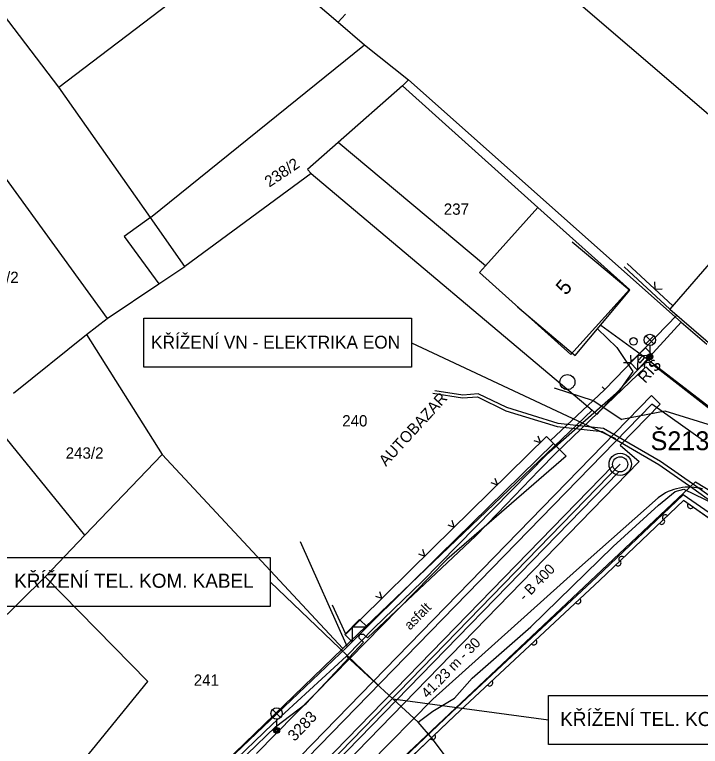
# Model space of a CAD drawing. Extents: x -601580 to 4, y -1204314 to 4.
# Drawn here: x -600487.22 to -600441.72, y -1203792.72 to -1203744.15 of the extents above; entities that cross this region are included whole.
import ezdxf

# ---------------------------------------------------------------- set-up
doc = ezdxf.new("R2010")
doc.units = 0
for name, color, linetype in [('00-EON NN', 7, 'Continuous'), ('00-EON VN', 7, 'Continuous'), ('00-KN-HRANICE PARCEL', 7, 'Continuous'), ('00-KN-PARC. CISLA', 7, 'Continuous'), ('00-KN-VNITRNI KRESBA', 7, 'Continuous'), ('00-POLOHOPIS', 7, 'Continuous'), ('00-SITE KOM. KABEL', 7, 'Continuous'), ('00-VAK-KANAL-POTRUBI', 7, 'Continuous'), ('00-VAK-VODA-RAD IGIS', 7, 'Continuous'), ('11-REKONSTRUKCE  VYKOP', 7, 'Continuous'), ('11-REKONSTRUKCE KANALIZACE', 7, 'Continuous'), ('11-REKONSTRUKCE KANALIZACE OSA', 7, 'Continuous'), ('11-REKONSTRUKCE KANALIZACE POPIS', 7, 'Continuous'), ('11-REKONSTRUKCE VODOVOD', 7, 'Continuous'), ('11-REKONSTRUKCE VODOVOD POPIS', 7, 'Continuous'), ('Vrstva 26', 7, 'Continuous'), ('Vrstva 27', 7, 'Continuous'), ('Vrstva 28', 7, 'Continuous'), ('Vrstva 33', 7, 'Continuous'), ('Vrstva 8', 7, 'Continuous'), ('Vrstva 9', 7, 'Continuous')]:
    doc.layers.add(name, color=color, linetype=linetype)

# ---------------------------------------------------------------- blocks, each defined once
blk = doc.blocks.new('6.14A_1004')
at = {"layer": 'Vrstva 28'}
blk.add_circle((0, 0), 0.25, dxfattribs=at)
blk = doc.blocks.new('6.20D_492')
at = {"layer": 'Vrstva 27'}
blk.add_circle((0, 0), 0.5, dxfattribs=at)
blk = doc.blocks.new('6.560_1100')
at = {"layer": 'Vrstva 33'}
for p, q in [((-0.265, 0.86), (0.265, 1.39)), ((-0.265, 1.39), (0.265, 0.86)), ((0, 0.75), (0, 0))]:
    blk.add_line(p, q, dxfattribs=at)
for centre, radius in [((0, 1.125), 0.375), ((0, 0), 0.2), ((0, 0), 0.145), ((0, 0), 0.0876)]:
    blk.add_circle(centre, radius, dxfattribs=at)
blk = doc.blocks.new('VSTUP_174')
at = {"layer": 'Vrstva 8'}
blk.add_line((0, 0.25), (0, 0), dxfattribs=at)
blk = doc.blocks.new('6.560_1102')
at = {"layer": 'Vrstva 33'}
for p, q in [((-0.265, 0.86), (0.265, 1.39)), ((-0.265, 1.39), (0.265, 0.86)), ((0, 0.75), (0, 0))]:
    blk.add_line(p, q, dxfattribs=at)
for centre, radius in [((0, 1.125), 0.375), ((0, 0), 0.2), ((0, 0), 0.145), ((0, 0), 0.0876)]:
    blk.add_circle(centre, radius, dxfattribs=at)
blk = doc.blocks.new('NN630')
at = {"layer": 'Vrstva 9'}
for points in [[(-3, -700), (-703, 0)], [(-703, -700), (-703, 0), (697, 0), (697, -700)], [(-3, -700), (697, 0)], [(-703, -700), (697, -700)]]:
    blk.add_lwpolyline(points, dxfattribs=at)

msp = doc.modelspace()

# ---------------------------------------------------------------- linework, layer by layer
at = {"layer": '00-EON NN'}
msp.add_lwpolyline([(-600473.672, -1203795.059), (-600469.91, -1203791.43), (-600467.871, -1203789.879), (-600464.07, -1203785.817), (-600464.347, -1203785.548), (-600464.327, -1203785.286), (-600464.065, -1203785.278), (-600463.799, -1203785.523), (-600456.609, -1203778.75), (-600455.185, -1203777.274), (-600452.407, -1203774.395), (-600451.32, -1203773.27), (-600447.396, -1203769.512), (-600445.375, -1203767.577), (-600445.434, -1203767.516), (-600445.39, -1203767.27), (-600445.152, -1203767.233), (-600444.955, -1203767.436), (-600444.789, -1203767.441), (-600443.789, -1203768.219), (-600439.988, -1203771.191)], dxfattribs=at)
at = {"layer": '00-EON VN'}
for points in [[(-600459.477, -1203769.291), (-600457.511, -1203769.594), (-600456.508, -1203769.518), (-600454.624, -1203770.445), (-600451.211, -1203771.488), (-600448.233, -1203771.815), (-600444.486, -1203774.019), (-600442.217, -1203775.59), (-600438.167, -1203778.496), (-600424.472, -1203787.735), (-600416.801, -1203792.528), (-600411.123, -1203796.487), (-600404.975, -1203801.537), (-600404.82, -1203801.644), (-600404.96, -1203802.62)], [(-600383.25, -1203783.59), (-600384.36, -1203785.06), (-600387.363, -1203790.788), (-600387.636, -1203791.819), (-600388.781, -1203794.246), (-600391.141, -1203798.544), (-600394.408, -1203804.965), (-600395.164, -1203806.243), (-600395.912, -1203806.852), (-600396.541, -1203806.795), (-600400.796, -1203804.12), (-600404.813, -1203801.302), (-600410.985, -1203796.316), (-600416.678, -1203792.351), (-600424.36, -1203787.555), (-600438.08, -1203778.28), (-600442.027, -1203775.462), (-600444.357, -1203773.807), (-600448.151, -1203771.631), (-600451.152, -1203771.298), (-600454.57, -1203770.237), (-600456.457, -1203769.325), (-600457.482, -1203769.405), (-600459.327, -1203769.119)]]:
    msp.add_lwpolyline(points, dxfattribs=at)
at = {"layer": '00-KN-HRANICE PARCEL'}
for p, q in [((-600478.21, -1203757.62), (-600464, -1203746.15)), ((-600464, -1203746.15), (-600461.08, -1203748.49)), ((-600461.08, -1203748.49), (-600442.99, -1203764.57)), ((-600467.55, -1203754.71), (-600475.93, -1203760.88)), ((-600467.55, -1203754.71), (-600448.91, -1203770.42)), ((-600482.45, -1203765.39), (-600481.08, -1203764.32)), ((-600442.99, -1203764.57), (-600441.29, -1203766.03)), ((-600487.29, -1203769.27), (-600482.45, -1203765.39)), ((-600482.45, -1203765.39), (-600477.42, -1203773.36)), ((-600465.44, -1203786.23), (-600448.91, -1203770.42)), ((-600482.55, -1203778.7), (-600489.05, -1203770.73)), ((-600477.42, -1203773.36), (-600482.55, -1203778.7)), ((-600477.42, -1203773.36), (-600465.44, -1203786.23))]:
    msp.add_line(p, q, dxfattribs=at)
for points in [[(-600469.34, -1203723.1), (-600466.22, -1203727.76), (-600462.39, -1203731.53), (-600461.96, -1203731.92), (-600457.59, -1203735.9), (-600452.74, -1203740.82), (-600433.78, -1203757.11)], [(-600480.16, -1203730.41), (-600471.78, -1203739.46), (-600469.52, -1203741.43), (-600465.75, -1203744.65), (-600464, -1203746.15)], [(-600478.21, -1203757.62), (-600484.29, -1203748.96), (-600487.61, -1203744.61), (-600491.59, -1203739.41)], [(-600461.08, -1203748.49), (-600461.48, -1203748.88), (-600465.75, -1203752.64), (-600467.78, -1203754.43), (-600467.55, -1203754.71)], [(-600495.99, -1203757.53), (-600497.89, -1203754.85), (-600498.89, -1203753.29), (-600498.57, -1203753.07), (-600497.03, -1203755.41), (-600490.66, -1203751.13), (-600481.08, -1203764.32)], [(-600475.93, -1203760.88), (-600478.05, -1203757.85), (-600478.21, -1203757.62)], [(-600481.08, -1203764.32), (-600477.64, -1203762.03), (-600475.93, -1203760.88)], [(-600448.91, -1203770.42), (-600448.58, -1203770.7), (-600442.99, -1203764.57)], [(-600490.56, -1203829.3), (-600473.65, -1203806.86), (-600467.29, -1203799), (-600442.04, -1203775.17), (-600437.14, -1203778.16)], [(-600482.55, -1203778.7), (-600485.2, -1203781.47), (-600490.18, -1203786.39), (-600492.01, -1203788.21), (-600491.04, -1203789.24), (-600495.44, -1203792.84)], [(-600486.72, -1203810.21), (-600473.25, -1203793.78), (-600465.44, -1203786.23)]]:
    msp.add_lwpolyline(points, dxfattribs=at)
at = {"layer": '00-KN-VNITRNI KRESBA'}
for p, q in [((-600484.29, -1203748.96), (-600471.78, -1203739.46)), ((-600465.27, -1203744.13), (-600465.75, -1203744.65)), ((-600461.48, -1203748.88), (-600452.5, -1203756.96)), ((-600455.97, -1203760.82), (-600465.75, -1203752.64)), ((-600455.97, -1203760.82), (-600452.5, -1203756.96)), ((-600452.5, -1203756.96), (-600446.43, -1203762.41)), ((-600478.21, -1203757.62), (-600479.94, -1203758.89)), ((-600479.94, -1203758.89), (-600477.64, -1203762.03)), ((-600456.37, -1203761.27), (-600455.97, -1203760.82)), ((-600450.31, -1203766.72), (-600456.37, -1203761.27)), ((-600446.43, -1203762.41), (-600450.31, -1203766.72)), ((-600478.38, -1203788.41), (-600485.2, -1203781.47)), ((-600489.46, -1203802.03), (-600478.38, -1203788.41))]:
    msp.add_line(p, q, dxfattribs=at)
at = {"layer": '00-POLOHOPIS'}
for p, q in [((-600450.221, -1203759.23), (-600446.395, -1203762.449)), ((-600440.476, -1203759.931), (-600443.745, -1203763.714)), ((-600446.581, -1203760.675), (-600443.548, -1203763.486)), ((-600443.745, -1203763.714), (-600446.785, -1203760.896)), ((-600450.034, -1203766.775), (-600446.395, -1203762.449)), ((-600453.86, -1203763.556), (-600450.034, -1203766.775)), ((-600448.055, -1203769.043), (-600443.291, -1203764.106)), ((-600443.745, -1203763.714), (-600432.317, -1203773.59)), ((-600445.86, -1203767.128), (-600445.567, -1203766.796)), ((-600445.711, -1203767.261), (-600445.418, -1203766.929)), ((-600445.418, -1203766.929), (-600445.567, -1203766.796)), ((-600445.86, -1203767.128), (-600445.721, -1203767.261)), ((-600451.431, -1203768.926), (-600448.827, -1203769.768)), ((-600448.827, -1203769.768), (-600448.055, -1203769.043)), ((-600448.827, -1203769.768), (-600448.055, -1203769.043)), ((-600451.671, -1203772.418), (-600448.827, -1203769.768)), ((-600451.671, -1203772.418), (-600448.827, -1203769.768)), ((-600448.827, -1203769.768), (-600446.92, -1203771.019)), ((-600444.049, -1203770.469), (-600446.92, -1203771.019)), ((-600439.816, -1203771.808), (-600444.049, -1203770.469)), ((-600459.471, -1203779.568), (-600451.925, -1203772.158)), ((-600451.925, -1203772.158), (-600451.47, -1203772.622)), ((-600459.02, -1203780.036), (-600451.47, -1203772.622)), ((-600451.47, -1203772.622), (-600450.627, -1203773.461)), ((-600450.627, -1203773.461), (-600458.536, -1203780.325)), ((-600444.521, -1203776.225), (-600449.943, -1203781.031)), ((-600442.871, -1203776.021), (-600448.591, -1203781.475)), ((-600430.741, -1203784.52), (-600442.871, -1203776.021)), ((-600442.841, -1203776.408), (-600448.383, -1203781.692)), ((-600430.913, -1203784.765), (-600442.841, -1203776.408)), ((-600468.263, -1203779.127), (-600465.151, -1203786.129)), ((-600464.272, -1203784.301), (-600459.471, -1203779.568)), ((-600463.811, -1203784.759), (-600459.02, -1203780.036)), ((-600458.536, -1203780.325), (-600466.057, -1203787.997)), ((-600449.943, -1203781.031), (-600459.469, -1203789.593)), ((-600448.591, -1203781.475), (-600458.24, -1203790.484)), ((-600448.386, -1203781.694), (-600458.041, -1203790.709)), ((-600465.237, -1203785.287), (-600466.118, -1203783.347)), ((-600465.237, -1203785.287), (-600464.272, -1203784.301)), ((-600465.151, -1203786.129), (-600463.811, -1203784.759)), ((-600473.056, -1203793.647), (-600465.151, -1203786.129)), ((-600466.057, -1203787.997), (-600471.165, -1203793.196)), ((-600459.469, -1203789.593), (-600467.784, -1203798.007)), ((-600458.24, -1203790.484), (-600464.245, -1203796.188)), ((-600458.041, -1203790.709), (-600464.03, -1203796.398))]:
    msp.add_line(p, q, dxfattribs=at)
for points in [[(-600446.581, -1203760.675), (-600443.548, -1203763.486)], [(-600444.766, -1203761.88), (-600444.747, -1203762.374), (-600444.253, -1203762.356)], [(-600448.055, -1203769.043), (-600443.291, -1203764.106)], [(-600446.814, -1203767.253), (-600446.319, -1203767.244), (-600446.328, -1203766.749)], [(-600459.471, -1203779.568), (-600451.925, -1203772.158)], [(-600452.759, -1203772.416), (-600452.336, -1203772.562), (-600452.473, -1203772.136)], [(-600451.925, -1203772.158), (-600451.47, -1203772.622)], [(-600455.613, -1203775.219), (-600455.19, -1203775.364), (-600455.328, -1203774.939)], [(-600448.383, -1203781.692), (-600442.841, -1203776.408)], [(-600448.383, -1203781.692), (-600442.841, -1203776.408)], [(-600448.383, -1203781.692), (-600442.841, -1203776.408)], [(-600430.913, -1203784.765), (-600442.841, -1203776.408)], [(-600458.467, -1203778.021), (-600458.044, -1203778.167), (-600458.182, -1203777.741)], [(-600464.272, -1203784.301), (-600459.471, -1203779.568)], [(-600460.422, -1203779.944), (-600459.999, -1203780.089), (-600460.138, -1203779.663)], [(-600458.041, -1203790.709), (-600448.386, -1203781.694)], [(-600458.041, -1203790.709), (-600448.386, -1203781.694)], [(-600463.271, -1203782.752), (-600462.848, -1203782.897), (-600462.986, -1203782.472)], [(-600458.041, -1203790.709), (-600464.03, -1203796.398)]]:
    msp.add_lwpolyline(points, dxfattribs=at)
for centre, radius, start, end in [((-600442.471, -1203778.842), 3.324, 74.039, 128.0674), ((-600442.379, -1203776.732), 0.2, 144.9827, 324.9856), ((-600444.288, -1203777.788), 0.2, 223.6334, 43.6362), ((-600444.04, -1203777.552), 0.2, 43.6334, 223.6362), ((-600446.935, -1203780.312), 0.2, 43.6334, 223.6362), ((-600447.183, -1203780.548), 0.2, 223.6334, 43.6362), ((-600449.848, -1203783.059), 0.2, 223.0352, 43.0381), ((-600452.771, -1203785.789), 0.2, 223.0352, 43.0381), ((-600455.695, -1203788.519), 0.2, 223.0352, 43.0381), ((-600459.491, -1203792.086), 0.2, 223.527, 43.5299)]:
    msp.add_arc(centre, radius, start, end, dxfattribs=at)
at = {"layer": '00-SITE KOM. KABEL'}
for points in [[(-600448.32, -1203764.77), (-600445.41, -1203766.9), (-600434.97, -1203774.92), (-600422.32, -1203783.12), (-600413.93, -1203789.04), (-600405.18, -1203794.93), (-600400.25, -1203797.98), (-600398.96, -1203798.36), (-600397.12, -1203797.36), (-600388.96, -1203781.95), (-600378.33, -1203762.13), (-600375.93, -1203758.23), (-600373.1, -1203754.01), (-600370.24, -1203749.96), (-600363.35, -1203740.04), (-600357.38, -1203731.69), (-600349.33, -1203720.15), (-600345.8, -1203715.19), (-600340.07, -1203706.96), (-600329.02, -1203689.27)], [(-600448.55, -1203765.01), (-600447.27, -1203766.25), (-600446.21, -1203767.84)], [(-600446.21, -1203767.84), (-600447.14, -1203769.15), (-600451.9, -1203773.36), (-600460.17, -1203781.78), (-600463.36, -1203784.86)], [(-600447.14, -1203769.15), (-600451.9, -1203773.36)], [(-600460.44, -1203791.11), (-600459.46, -1203790.39), (-600458.03, -1203789.53), (-600456.87, -1203788.19), (-600452.97, -1203784.79), (-600447.51, -1203779.45), (-600444.5, -1203776.72), (-600443.4, -1203775.81), (-600442.82, -1203775.66), (-600440.03, -1203777)], [(-600463.36, -1203784.86), (-600465.19, -1203786.74)], [(-600477.51, -1203798.97), (-600477.33, -1203799.12), (-600473.04, -1203794.08), (-600470.1, -1203791.26), (-600465.19, -1203786.74)], [(-600460.44, -1203791.11), (-600465.19, -1203786.74)], [(-600460.44, -1203791.11), (-600465.19, -1203786.74)], [(-600459.49, -1203792.23), (-600460.44, -1203791.11)], [(-600456.27, -1203796.31), (-600456.73, -1203795.91), (-600459.49, -1203792.23)], [(-600455.71, -1203797.64), (-600456.27, -1203796.31), (-600456.73, -1203795.91), (-600459.49, -1203792.23)]]:
    msp.add_lwpolyline(points, dxfattribs=at)
at = {"layer": '00-VAK-KANAL-POTRUBI'}
msp.add_circle((-600447.04, -1203774.002), 0.5, dxfattribs=at)
at = {"layer": '00-VAK-VODA-RAD IGIS'}
msp.add_lwpolyline([(-600395.742, -1203804.116), (-600404.972, -1203798.52), (-600440.983, -1203772.83), (-600444.948, -1203770.012)], dxfattribs=at)
at = {"layer": '11-REKONSTRUKCE  VYKOP'}
for p, q in [((-600444.956, -1203769.446), (-600444.383, -1203770.004)), ((-600447.033, -1203772.727), (-600445.772, -1203773.818)), ((-600445.772, -1203773.818), (-600475.196, -1203804.047))]:
    msp.add_line(p, q, dxfattribs=at)
for points in [[(-600500.747, -1203836.125), (-600477.095, -1203802.472), (-600444.956, -1203769.446)], [(-600447.033, -1203772.727), (-600444.383, -1203770.004)]]:
    msp.add_lwpolyline(points, dxfattribs=at)
at = {"layer": '11-REKONSTRUKCE KANALIZACE'}
for p, q in [((-600447.53, -1203774.104), (-600475.521, -1203802.862)), ((-600447.129, -1203774.495), (-600475.12, -1203803.252))]:
    msp.add_line(p, q, dxfattribs=at)
for radius in [0.74, 0.5]:
    msp.add_circle((-600447.04, -1203774.002), radius, dxfattribs=at)
at = {"layer": '11-REKONSTRUKCE KANALIZACE OSA'}
msp.add_line((-600447.04, -1203774.002), (-600475.798, -1203803.548), dxfattribs=at)
at = {"layer": '11-REKONSTRUKCE KANALIZACE POPIS'}
msp.add_line((-600451.8, -1203790.984), (-600462.129, -1203789.593), dxfattribs=at)
msp.add_lwpolyline([(-600451.8, -1203789.358), (-600434.043, -1203789.358), (-600434.043, -1203792.609), (-600451.8, -1203792.609)], close=True, dxfattribs=at)
at = {"layer": '11-REKONSTRUKCE VODOVOD'}
msp.add_lwpolyline([(-600500.42, -1203836.355), (-600476.786, -1203802.728), (-600444.948, -1203770.012)], dxfattribs=at)
at = {"layer": '11-REKONSTRUKCE VODOVOD POPIS'}
for p, q in [((-600460.886, -1203765.935), (-600447.342, -1203772.283)), ((-600470.271, -1203781.806), (-600463.098, -1203788.665))]:
    msp.add_line(p, q, dxfattribs=at)
for points in [[(-600478.644, -1203764.309), (-600460.886, -1203764.309), (-600460.886, -1203767.561), (-600478.644, -1203767.561)], [(-600488.028, -1203780.18), (-600470.271, -1203780.18), (-600470.271, -1203783.431), (-600488.028, -1203783.431)]]:
    msp.add_lwpolyline(points, close=True, dxfattribs=at)

# ---------------------------------------------------------------- block references
at = {"layer": '00-POLOHOPIS'}
for name, p in [('6.14A_1004', (-600446.158, -1203765.843)), ('6.560_1100', (-600445.072, -1203766.871)), ('6.560_1102', (-600469.835, -1203791.669))]:
    msp.add_blockref(name, p, dxfattribs=at)
for name, p, xscale, yscale, rotation in [('6.20D_492', (-600450.542, -1203768.544), 0.9999972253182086, 0.9999972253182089, -40.83335804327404), ('VSTUP_174', (-600448.055, -1203769.043), 1.00000008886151, 1.00000008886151, 43.20178064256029)]:
    msp.add_blockref(name, p, dxfattribs=dict(at, xscale=xscale, yscale=yscale, rotation=rotation))
at = {"layer": 'Vrstva 26'}
for p, xscale, yscale, rotation in [((-600445.39, -1203767.27), 0.0009999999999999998, 0.001, -136.25214160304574), ((-600464.328, -1203785.286), 0.0010000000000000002, 0.0010000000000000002, -134.36575553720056)]:
    msp.add_blockref('NN630', p, dxfattribs=dict(at, xscale=xscale, yscale=yscale, rotation=rotation))

# ---------------------------------------------------------------- texts
at = {"layer": '00-KN-PARC. CISLA'}
for s, rotation, p in [('238/2', 34, (-600470.317, -1203755.643)), ('3283', 46.5074, (-600468.638, -1203792.435))]:
    msp.add_text(s, height=0.75, rotation=rotation, dxfattribs=at).set_placement(p)
for s, p in [('237', (-600458.744, -1203757.44)), ('239/2', (-600489.46, -1203761.97)), ('240', (-600465.484, -1203771.49)), ('243/2', (-600483.83, -1203773.63)), ('241', (-600475.332, -1203788.7))]:
    msp.add_text(s, height=0.75, dxfattribs=at).set_placement(p)
at = {"layer": '00-POLOHOPIS'}
for s, height, rotation, p in [('5', 1, 49.9297, (-600450.641, -1203762.838)), ('RIS', 0.75, 47.6148, (-600445.378, -1203768.668)), ('AUTOBAZAR', 0.75, 47.6148, (-600462.579, -1203774.184)), (' asfalt', 0.65, 45.5694, (-600461.148, -1203785.217))]:
    msp.add_text(s, height=height, rotation=rotation, dxfattribs=at).set_placement(p)
at = {"layer": '11-REKONSTRUKCE KANALIZACE POPIS'}
for s, height, p in [('Š213.b', 1.25, (-600445.025, -1203773.065)), ('KŘÍŽENÍ TEL. KOM. KABEL', 0.9375, (-600451.017, -1203791.376))]:
    msp.add_text(s, height=height, dxfattribs=at).set_placement(p)
for s, height, p in [('- B 400', 0.6824, (-600453.364, -1203783.123)), ('41.23 m - 30', 0.68241, (-600459.823, -1203789.575))]:
    msp.add_text(s, height=height, rotation=45.7568, dxfattribs=at).set_placement(p)
at = {"layer": '11-REKONSTRUKCE VODOVOD POPIS'}
for s, height, p in [('KŘÍŽENÍ VN - ELEKTRIKA EON', 0.85549, (-600478.168, -1203766.323)), ('KŘÍŽENÍ TEL. KOM. KABEL', 0.9375, (-600487.245, -1203782.199))]:
    msp.add_text(s, height=height, dxfattribs=at).set_placement(p)

doc.saveas('drawing.dxf')
